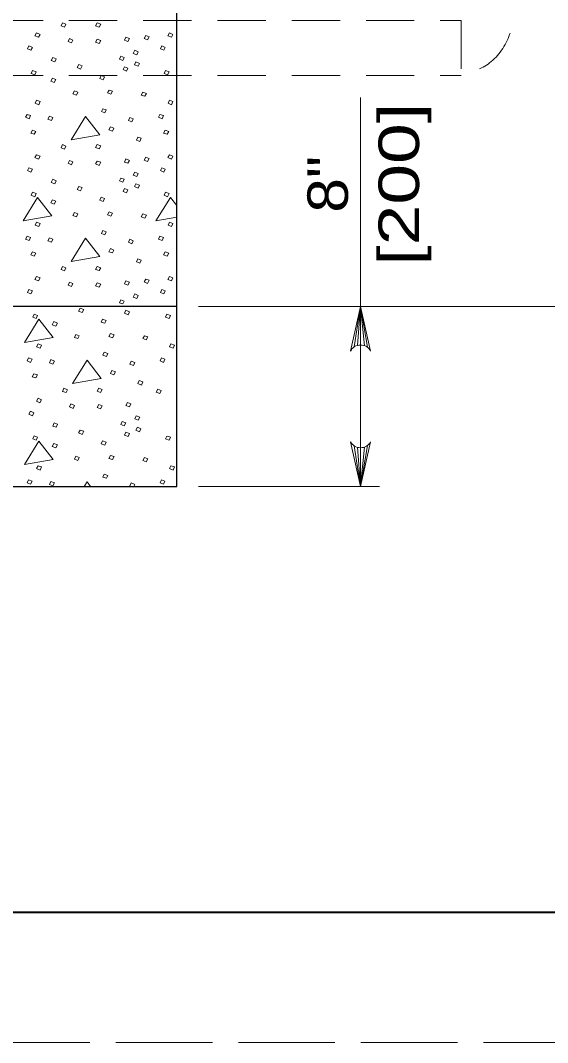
# Model space of a CAD drawing. Extents: x 1083.1 to 1123, y 697.4 to 741.4.
# Drawn here: x 1094.559 to 1096.589, y 697.354 to 701.287 of the extents above; entities that cross this region are included whole.
import ezdxf
from ezdxf.enums import TextEntityAlignment as Align

# ---------------------------------------------------------------- set-up
doc = ezdxf.new("R2010")
doc.units = 0
doc.header["$LTSCALE"] = 0.062
doc.linetypes.add('LONG_DASHED', pattern=[7.5, 6, -1.5])
doc.linetypes.add('MEDIUM_DASHED', pattern=[4.5, 3, -1.5])
doc.layers.add('1', color=7, linetype='Continuous', lineweight=13)

msp = doc.modelspace()

# ---------------------------------------------------------------- linework, layer by layer
at = {"layer": '1', "lineweight": 25}
for p, q in [((1095.16083, 699.49442), (1095.16083, 704.3885)), ((1095.16083, 700.18692), (1088.74, 700.18692))]:
    msp.add_line(p, q, dxfattribs=at)
at = {"layer": '1', "linetype": 'MEDIUM_DASHED'}
for p, q in [((1094.45983, 701.28742), (1096.25675, 701.28742)), ((1096.25675, 701.28742), (1096.25675, 701.07533)), ((1094.45983, 701.07533), (1096.25675, 701.07533))]:
    msp.add_line(p, q, dxfattribs=at)
at = {"layer": '1'}
for p, q in [((1095.86883, 699.49442), (1095.86883, 700.99042)), ((1095.16083, 700.57467), (1095.1365, 700.60592)), ((1095.24508, 700.18692), (1100.93725, 700.18692)), ((1095.84467, 700.03142), (1095.86883, 700.18692)), ((1095.85658, 700.03667), (1095.86883, 700.18692)), ((1095.86883, 700.03833), (1095.86883, 700.18692)), ((1095.88433, 700.03558), (1095.86883, 700.18692)), ((1095.89558, 700.02958), (1095.86883, 700.18692)), ((1095.84467, 699.64992), (1095.86883, 699.49442)), ((1095.85658, 699.64467), (1095.86883, 699.49442)), ((1095.89558, 699.65175), (1095.86883, 699.49442)), ((1095.88433, 699.64583), (1095.86883, 699.49442)), ((1095.86883, 699.64308), (1095.86883, 699.49442)), ((1094.81533, 699.51175), (1094.80458, 699.49442)), ((1094.82883, 699.49442), (1094.81533, 699.51175)), ((1095.24508, 699.49442), (1095.94233, 699.49442))]:
    msp.add_line(p, q, dxfattribs=at)
at = {"layer": '1', "linetype": 'LONG_DASHED'}
msp.add_lwpolyline([(1083.12642, 697.35408), (1117.12642, 697.35408), (1117.12642, 719.35408), (1083.12642, 719.35408)], close=True, dxfattribs=at)
at = {"layer": '1', "lineweight": 25}
for points in [[(1116.62642, 697.85408), (1085.12642, 697.85408), (1085.12642, 718.85408)], [(1088.02083, 699.97467), (1088.02083, 699.49442), (1095.16083, 699.49442)]]:
    msp.add_lwpolyline(points, dxfattribs=at)
at = {"layer": '1', "lineweight": 40}
msp.add_lwpolyline([(1085.12642, 718.85408), (1116.62642, 718.85408), (1116.62642, 697.85408), (1085.12642, 697.85408)], close=True, dxfattribs=at)
at = {"layer": '1'}
for points in [[(1094.72067, 701.27825), (1094.73417, 701.27258), (1094.72883, 701.26133), (1094.71533, 701.26617)], [(1094.8545, 701.27825), (1094.868, 701.27342), (1094.86167, 701.26208), (1094.84825, 701.267)], [(1094.621, 701.2395), (1094.6345, 701.23383), (1094.62825, 701.2225), (1094.61475, 701.22817)], [(1095.13292, 701.2395), (1095.14633, 701.23383), (1095.14008, 701.2225), (1095.12658, 701.22817)], [(1094.74767, 701.21767), (1094.76108, 701.212), (1094.75575, 701.20067), (1094.74225, 701.20633)], [(1094.8545, 701.21525), (1094.868, 701.21042), (1094.86167, 701.19825), (1094.84825, 701.20392)], [(1094.965, 701.22333), (1094.97842, 701.21767), (1094.97308, 701.20633), (1094.95958, 701.21117)], [(1095.04133, 701.22983), (1095.05475, 701.22492), (1095.0485, 701.21283), (1095.035, 701.2185)], [(1094.59142, 701.18942), (1094.60492, 701.18375), (1094.5995, 701.17242), (1094.586, 701.17808)], [(1094.99908, 701.17242), (1095.01258, 701.16675), (1095.00717, 701.15542), (1094.99367, 701.16033)], [(1095.10325, 701.18942), (1095.11675, 701.18375), (1095.11133, 701.17242), (1095.09783, 701.17808)], [(1094.683, 701.14492), (1094.6965, 701.13925), (1094.69108, 701.128), (1094.67758, 701.13283)], [(1094.94517, 701.14983), (1094.95867, 701.14492), (1094.95333, 701.13367), (1094.93983, 701.1385)], [(1095.00358, 701.128), (1095.01708, 701.12233), (1095.01167, 701.111), (1094.99817, 701.11667)], [(1094.60575, 701.09483), (1094.61925, 701.09), (1094.61383, 701.07783), (1094.60042, 701.0835)], [(1094.78358, 701.1175), (1094.797, 701.11258), (1094.79075, 701.1005), (1094.77725, 701.10617)], [(1094.95958, 701.10942), (1094.97308, 701.10375), (1094.96767, 701.09242), (1094.95417, 701.09808)], [(1095.11767, 701.09483), (1095.13108, 701.09), (1095.12575, 701.07783), (1095.11225, 701.0835)], [(1094.68208, 701.06575), (1094.69558, 701.06008), (1094.68925, 701.04875), (1094.67583, 701.05367)], [(1094.86975, 701.07542), (1094.88325, 701.07058), (1094.87783, 701.05925), (1094.86442, 701.06417)], [(1094.7665, 701.01642), (1094.78, 701.01158), (1094.77458, 701.00033), (1094.76108, 701.00517)], [(1094.90033, 701.01967), (1094.91375, 701.01483), (1094.9075, 701.0035), (1094.894, 701.00833)], [(1095.0305, 701.01158), (1095.044, 701.00675), (1095.03767, 700.99542), (1095.02425, 701.00033)], [(1094.621, 700.98008), (1094.6345, 700.97525), (1094.62908, 700.96308), (1094.61567, 700.96875)], [(1095.13292, 700.98008), (1095.14633, 700.97525), (1095.141, 700.96308), (1095.1275, 700.96875)], [(1094.58425, 700.92592), (1094.59767, 700.92108), (1094.59225, 700.909), (1094.57883, 700.91467)], [(1094.87608, 700.94775), (1094.8895, 700.94292), (1094.88417, 700.93158), (1094.87067, 700.93642)], [(1095.09608, 700.92592), (1095.10958, 700.92108), (1095.10417, 700.909), (1095.09067, 700.91467)], [(1094.67042, 700.9195), (1094.68392, 700.91383), (1094.6785, 700.9025), (1094.665, 700.90733)], [(1094.80958, 700.91783), (1094.75392, 700.82817), (1094.86442, 700.84758)], [(1094.98025, 700.91383), (1094.99367, 700.90817), (1094.98833, 700.89683), (1094.97483, 700.9025)], [(1094.60492, 700.86533), (1094.61833, 700.8605), (1094.61208, 700.84917), (1094.59858, 700.854)], [(1094.90567, 700.87825), (1094.91917, 700.87258), (1094.91292, 700.86133), (1094.89942, 700.86617)], [(1095.11675, 700.86533), (1095.13017, 700.8605), (1095.12392, 700.84917), (1095.11042, 700.854)], [(1094.72067, 700.80958), (1094.73417, 700.80392), (1094.72883, 700.79258), (1094.71533, 700.79742)], [(1094.8545, 700.80958), (1094.868, 700.80475), (1094.86167, 700.79342), (1094.84825, 700.79825)], [(1095.01075, 700.83867), (1095.02425, 700.83383), (1095.01883, 700.82167), (1095.00542, 700.82733)], [(1094.621, 700.77075), (1094.6345, 700.76517), (1094.62825, 700.75383), (1094.61475, 700.7595)], [(1095.13292, 700.77075), (1095.14633, 700.76517), (1095.14008, 700.75383), (1095.12658, 700.7595)], [(1094.74767, 700.749), (1094.76108, 700.74333), (1094.75575, 700.732), (1094.74225, 700.73767)], [(1094.8545, 700.7465), (1094.868, 700.74167), (1094.86167, 700.72958), (1094.84825, 700.73525)], [(1094.965, 700.75467), (1094.97842, 700.749), (1094.97308, 700.73767), (1094.95958, 700.7425)], [(1095.04133, 700.76108), (1095.05475, 700.75625), (1095.0485, 700.74408), (1095.035, 700.74975)], [(1094.59142, 700.72067), (1094.60492, 700.715), (1094.5995, 700.70375), (1094.586, 700.70933)], [(1094.99908, 700.70375), (1095.01258, 700.69808), (1095.00717, 700.68675), (1094.99367, 700.69158)], [(1095.10325, 700.72067), (1095.11675, 700.715), (1095.11133, 700.70375), (1095.09783, 700.70933)], [(1094.683, 700.67625), (1094.6965, 700.67058), (1094.69108, 700.65925), (1094.67758, 700.66408)], [(1094.78358, 700.64875), (1094.797, 700.64392), (1094.79075, 700.63175), (1094.77725, 700.63742)], [(1094.94517, 700.68108), (1094.95867, 700.67625), (1094.95333, 700.66492), (1094.93983, 700.66975)], [(1095.00358, 700.65925), (1095.01708, 700.65358), (1095.01167, 700.64233), (1094.99817, 700.64792)], [(1094.60575, 700.62617), (1094.61925, 700.62125), (1094.61383, 700.60917), (1094.60042, 700.61483)], [(1094.86975, 700.60675), (1094.88325, 700.60192), (1094.87783, 700.59058), (1094.86442, 700.59542)], [(1094.95958, 700.64067), (1094.97308, 700.635), (1094.96767, 700.62375), (1094.95417, 700.62933)], [(1095.11767, 700.62617), (1095.13108, 700.62125), (1095.12575, 700.60917), (1095.11225, 700.61483)], [(1094.62467, 700.60592), (1094.56892, 700.51625), (1094.67942, 700.53567)], [(1094.68208, 700.597), (1094.69558, 700.59142), (1094.68925, 700.58008), (1094.67583, 700.58492)], [(1094.7665, 700.54775), (1094.78, 700.54292), (1094.77458, 700.53158), (1094.76108, 700.53642)], [(1094.90033, 700.551), (1094.91375, 700.54617), (1094.9075, 700.53483), (1094.894, 700.53967)], [(1095.0305, 700.54292), (1095.044, 700.53808), (1095.03767, 700.52675), (1095.02425, 700.53158)], [(1094.621, 700.51133), (1094.6345, 700.5065), (1094.62908, 700.49442), (1094.61567, 700.50008)], [(1095.13292, 700.51133), (1095.14633, 700.5065), (1095.141, 700.49442), (1095.1275, 700.50008)], [(1094.58425, 700.45725), (1094.59767, 700.45242), (1094.59225, 700.44025), (1094.57883, 700.44592)], [(1094.67042, 700.45075), (1094.68392, 700.44508), (1094.6785, 700.43383), (1094.665, 700.43867)], [(1094.87608, 700.47908), (1094.8895, 700.47425), (1094.88417, 700.46292), (1094.87067, 700.46775)], [(1095.09608, 700.45725), (1095.10958, 700.45242), (1095.10417, 700.44025), (1095.09067, 700.44592)], [(1094.80958, 700.44917), (1094.75392, 700.35942), (1094.86442, 700.37883)], [(1094.98025, 700.44508), (1094.99367, 700.43942), (1094.98833, 700.42817), (1094.97483, 700.43383)], [(1094.60492, 700.39658), (1094.61833, 700.39175), (1094.61208, 700.3805), (1094.59858, 700.38533)], [(1094.90567, 700.40958), (1094.91917, 700.40392), (1094.91292, 700.39258), (1094.89942, 700.39742)], [(1095.11675, 700.39658), (1095.13017, 700.39175), (1095.12392, 700.3805), (1095.11042, 700.38533)], [(1094.72067, 700.34083), (1094.73417, 700.33517), (1094.72883, 700.32392), (1094.71533, 700.32875)], [(1094.8545, 700.34083), (1094.868, 700.336), (1094.86167, 700.32467), (1094.84825, 700.32958)], [(1095.01075, 700.37), (1095.02425, 700.36508), (1095.01883, 700.353), (1095.00542, 700.35867)], [(1094.621, 700.30208), (1094.6345, 700.29642), (1094.62825, 700.28508), (1094.61475, 700.29075)], [(1095.04133, 700.29242), (1095.05475, 700.2875), (1095.0485, 700.27542), (1095.035, 700.28108)], [(1095.13292, 700.30208), (1095.14633, 700.29642), (1095.14008, 700.28508), (1095.12658, 700.29075)], [(1094.74767, 700.28025), (1094.76108, 700.27458), (1094.75575, 700.26325), (1094.74225, 700.26892)], [(1094.8545, 700.27783), (1094.868, 700.273), (1094.86167, 700.26083), (1094.84825, 700.2665)], [(1094.965, 700.28592), (1094.97842, 700.28025), (1094.97308, 700.26892), (1094.95958, 700.27383)], [(1094.59142, 700.252), (1094.60492, 700.24633), (1094.5995, 700.235), (1094.586, 700.24067)], [(1094.99908, 700.235), (1095.01258, 700.22933), (1095.00717, 700.218), (1094.99367, 700.22292)], [(1095.10325, 700.252), (1095.11675, 700.24633), (1095.11133, 700.235), (1095.09783, 700.24067)], [(1094.78933, 700.18008), (1094.80275, 700.17517), (1094.7965, 700.16308), (1094.783, 700.16875)], [(1094.94517, 700.21242), (1094.95867, 700.2075), (1094.95333, 700.19625), (1094.93983, 700.20108)], [(1094.63033, 700.13725), (1094.57467, 700.0475), (1094.68508, 700.06692)], [(1094.6115, 700.15742), (1094.62492, 700.15258), (1094.61958, 700.14042), (1094.60608, 700.14608)], [(1094.8755, 700.138), (1094.889, 700.13317), (1094.88358, 700.12183), (1094.87008, 700.12675)], [(1094.96533, 700.172), (1094.97875, 700.16633), (1094.97342, 700.155), (1094.95992, 700.16067)], [(1095.12333, 700.15742), (1095.13683, 700.15258), (1095.13142, 700.14042), (1095.11792, 700.14608)], [(1094.68783, 700.12833), (1094.70125, 700.12267), (1094.695, 700.11133), (1094.6815, 700.11625)], [(1094.77225, 700.079), (1094.78567, 700.07417), (1094.78033, 700.06283), (1094.76683, 700.06775)], [(1094.906, 700.08225), (1094.9195, 700.07742), (1094.91325, 700.06608), (1094.89975, 700.07092)], [(1095.03625, 700.07417), (1095.04975, 700.06933), (1095.04342, 700.058), (1095.02992, 700.06283)], [(1094.62675, 700.04267), (1094.64025, 700.03783), (1094.63483, 700.02567), (1094.62133, 700.03133)], [(1095.13858, 700.04267), (1095.15208, 700.03783), (1095.14667, 700.02567), (1095.13325, 700.03133)], [(1094.58992, 699.9885), (1094.60342, 699.98367), (1094.598, 699.97158), (1094.58458, 699.97725)], [(1094.67617, 699.98208), (1094.68958, 699.97642), (1094.68425, 699.96508), (1094.67075, 699.96992)], [(1094.81533, 699.98042), (1094.75967, 699.89075), (1094.87008, 699.91017)], [(1094.88175, 700.01033), (1094.89525, 700.0055), (1094.88983, 699.99417), (1094.87642, 699.999)], [(1095.10183, 699.9885), (1095.11525, 699.98367), (1095.10983, 699.97158), (1095.09642, 699.97725)], [(1094.91142, 699.94083), (1094.92492, 699.93517), (1094.91858, 699.92383), (1094.90517, 699.92875)], [(1094.98592, 699.97642), (1094.99942, 699.97075), (1094.994, 699.95942), (1094.98058, 699.96508)], [(1094.61058, 699.92792), (1094.62408, 699.92308), (1094.61775, 699.91175), (1094.60433, 699.91658)], [(1095.0165, 699.90125), (1095.02992, 699.89642), (1095.02458, 699.88425), (1095.01108, 699.88992)], [(1094.72642, 699.87217), (1094.73992, 699.8665), (1094.7345, 699.85517), (1094.721, 699.86)], [(1094.86025, 699.87217), (1094.87367, 699.86733), (1094.86742, 699.856), (1094.85392, 699.86083)], [(1095.08742, 699.869), (1095.10092, 699.86333), (1095.0955, 699.85208), (1095.08208, 699.85692)], [(1094.62675, 699.83342), (1094.64025, 699.82775), (1094.63392, 699.81642), (1094.6205, 699.82208)], [(1094.59708, 699.78325), (1094.61058, 699.77758), (1094.60517, 699.76625), (1094.59175, 699.77192)], [(1094.75333, 699.81158), (1094.76683, 699.80592), (1094.76142, 699.79458), (1094.748, 699.80025)], [(1094.86025, 699.80908), (1094.87367, 699.80425), (1094.86742, 699.79217), (1094.85392, 699.79783)], [(1094.97067, 699.81725), (1094.98417, 699.81158), (1094.97875, 699.80025), (1094.96533, 699.80508)], [(1094.95092, 699.74367), (1094.96442, 699.73883), (1094.959, 699.7275), (1094.9455, 699.73233)], [(1095.00483, 699.76625), (1095.01825, 699.76067), (1095.01292, 699.74933), (1094.99942, 699.75417)], [(1094.68875, 699.73883), (1094.70217, 699.73317), (1094.69683, 699.72183), (1094.68333, 699.72667)], [(1094.78933, 699.71133), (1094.80275, 699.7065), (1094.7965, 699.69433), (1094.783, 699.7)], [(1094.96533, 699.70325), (1094.97875, 699.69758), (1094.97342, 699.68625), (1094.95992, 699.69192)], [(1095.00933, 699.72183), (1095.02275, 699.71617), (1095.01742, 699.70492), (1095.00392, 699.7105)], [(1094.63033, 699.6685), (1094.57467, 699.57883), (1094.68508, 699.59825)], [(1094.6115, 699.68875), (1094.62492, 699.68383), (1094.61958, 699.67175), (1094.60608, 699.67742)], [(1094.8755, 699.66933), (1094.889, 699.6645), (1094.88358, 699.65317), (1094.87008, 699.658)], [(1094.68783, 699.65967), (1094.70125, 699.654), (1094.695, 699.64267), (1094.6815, 699.6475)], [(1094.77225, 699.61033), (1094.78567, 699.6055), (1094.78033, 699.59417), (1094.76683, 699.599)], [(1094.906, 699.61358), (1094.9195, 699.60875), (1094.91325, 699.59742), (1094.89975, 699.60225)], [(1095.03625, 699.6055), (1095.04975, 699.60067), (1095.04342, 699.58933), (1095.02992, 699.59417)], [(1094.62675, 699.574), (1094.64025, 699.56908), (1094.63483, 699.557), (1094.62133, 699.56267)], [(1095.13858, 699.574), (1095.15208, 699.56908), (1095.14667, 699.557), (1095.13325, 699.56267)], [(1094.58992, 699.51983), (1094.60342, 699.515), (1094.598, 699.50283), (1094.58458, 699.5085)], [(1094.67617, 699.51333), (1094.68958, 699.50767), (1094.68425, 699.49642), (1094.67075, 699.50125)], [(1094.88175, 699.54167), (1094.89525, 699.53675), (1094.88983, 699.5255), (1094.87642, 699.53033)], [(1095.10183, 699.51983), (1095.11525, 699.515), (1095.10983, 699.50283), (1095.09642, 699.5085)]]:
    msp.add_lwpolyline(points, close=True, dxfattribs=at)
for points in [[(1095.1365, 700.60592), (1095.08083, 700.51625), (1095.16083, 700.53033)], [(1095.907, 700.01517), (1095.86883, 700.18692), (1095.83067, 700.01517)], [(1095.12458, 699.68825), (1095.13683, 699.68383), (1095.13142, 699.67175), (1095.11792, 699.67742), (1095.12317, 699.68825)], [(1095.907, 699.66617), (1095.86883, 699.49442), (1095.83067, 699.66617)], [(1094.98517, 699.49442), (1094.98058, 699.49642), (1094.98592, 699.50767)], [(1094.98592, 699.50767), (1094.99942, 699.50208), (1094.99583, 699.49442)]]:
    msp.add_lwpolyline(points, dxfattribs=at)
for centre, start_param, end_param in [((1095.86878, 700.0013), 3.5270669, 5.8976801), ((1095.86878, 699.68006), 0.3855052, 2.7561184)]:
    msp.add_ellipse(centre, major_axis=(-0.04119, 0), ratio=0.9, start_param=start_param, end_param=end_param, dxfattribs=at)
at = {"layer": '1', "linetype": 'MEDIUM_DASHED'}
msp.add_spline([(1096.26467, 702.0505), (1096.3095, 701.95358), (1096.35508, 701.86883), (1096.41217, 701.7445), (1096.45117, 701.617), (1096.47833, 701.49367), (1096.47042, 701.384), (1096.44308, 701.23358), (1096.36575, 701.124), (1096.25675, 701.07533)], degree=3, dxfattribs=at)

# ---------------------------------------------------------------- texts
at = {"layer": '1'}
for s, width, p in [('[200]', 1.35, (1096.09417, 700.65683)), ('8"', 1.15, (1095.82017, 700.65683))]:
    msp.add_text(s, height=0.156, rotation=90, dxfattribs=dict(at, width=width)).set_placement(p, align=Align.CENTER)

doc.saveas('drawing.dxf')
